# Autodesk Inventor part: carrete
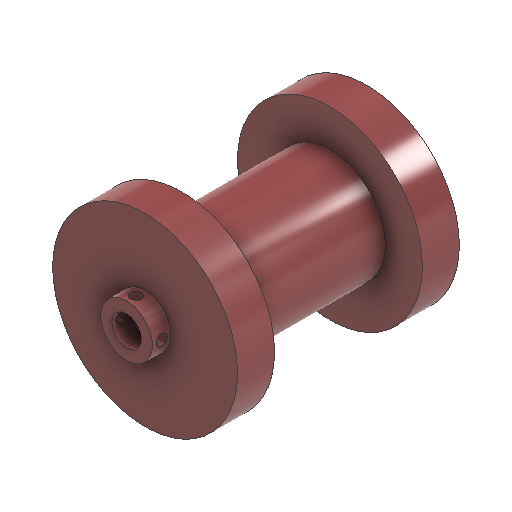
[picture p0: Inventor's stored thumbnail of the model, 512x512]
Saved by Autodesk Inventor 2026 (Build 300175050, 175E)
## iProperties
Created: 2025-06
Part Number: carrete
Material: Genérico
Document SubType Name: Modeling
Designer: piero
Density: 1 g/cm^3
Appearance: Valor por defecto
Author: piero
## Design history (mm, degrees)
sketch "Boceto1"
  geometry: C1 r 25 at (0, 0); C2 r 4 at (0, 0); C3 r 11 at (0, 0); 1 further point
  constraints: 3 centre point, 3 coincident
  dimensions: "d0" = 50 diameter of C1; "d3" = 8 diameter of C2; "d34" = 22 diameter of C3
extrude "Extrusión1" new body sketch "Boceto1" distance "d1" = 10; taper "d2" = 0 deg
sketch "Boceto5"
  geometry: C1 r 5 at (0, 0); C2 r 15 at (0, 0); 1 further point
  constraints: 2 centre point, 2 coincident
  dimensions: "d15" = 10 diameter of C1; "d16" = 30 diameter of C2
extrude "Extrusión5" join sketch "Boceto5" distance "d17" = 40; taper "d18" = 0 deg
sketch "Boceto6"
  geometry: C1 r 4 at (0, 0) reference; C2 r 25 at (0, 0); C3 r 4 at (0, 0); C4 r 5 at (0, 0) reference; C5 r 11 at (0, 0); 1 further point
  constraints: 3 centre point, 2 coincident
  dimensions: "d22" = 50 diameter of C2; "d30" = 8 diameter of C3; "d31" = 22 diameter of C5
extrude "Extrusión6" join sketch "Boceto6" distance "d23" = 10; taper "d24" = 0 deg
sketch "Boceto10"
  geometry: C1 r 7 at (0, 0); C2 r 4 at (0, 0); 1 further point
  constraints: 2 centre point, 2 coincident
  dimensions: "d41" = 14 diameter of C1; "d42" = 8 diameter of C2
extrude "Extrusión11" join sketch "Boceto10" distance "d43" = 5; taper "d44" = 0 deg
sketch "Boceto11"
  geometry: C1 r 4 at (0, 0); C2 r 7 at (0, 0); 1 further point
  constraints: 2 centre point, 2 coincident
  dimensions: "d45" = 8 diameter of C1; "d46" = 14 diameter of C2
extrude "Extrusión12" join sketch "Boceto11" distance "d47" = 5; taper "d48" = 0 deg
sketch "Boceto12"
  geometry: C1 r 1.5 at (0, 62.5); C2 r 1.5 at (0, -2.506); 1 further point
  constraints: 2 centre point
  dimensions: "d49" = 3 diameter of C1; "d50" = 3 diameter of C2
hole "Agujero1" sketch "Boceto12" at (0, 62.5) diameter "d51" = 3; stored, may be unused: countersink angle "d55" = 90 deg, drill point angle "d57" = 118 deg; dims "d52" = 6, "d53" = 4, "d54" = 2, "d56" = 8
sketch "Boceto13"
  geometry: C1 r 1.5 at (0, 62.453); C2 r 1.5 at (0, -2.49); 1 further point
  constraints: 2 centre point
  dimensions: "d58" = 3 diameter of C1; "d59" = 3 diameter of C2
hole "Agujero2" sketch "Boceto13" at (0, -2.49) diameter "d60" = 3; stored, may be unused: countersink angle "d64" = 90 deg, drill point angle "d66" = 118 deg; dims "d61" = 6, "d62" = 4, "d63" = 2, "d65" = 8
sketch "Boceto14"
  geometry: C1 r 1.5 at (0, 62.513); C2 r 1.5 at (0, -2.378); 1 further point
  constraints: 2 centre point
  dimensions: "d67" = 3 diameter of C1; "d68" = 3 diameter of C2
hole "Agujero3" sketch "Boceto14" diameter "d69" = 3; stored, may be unused: countersink angle "d73" = 90 deg, drill point angle "d75" = 118 deg; dims "d70" = 6, "d71" = 4, "d72" = 2, "d74" = 8
hole "Agujero4" sketch "Boceto14" diameter "d76" = 3; stored, may be unused: countersink angle "d80" = 90 deg, drill point angle "d82" = 118 deg; dims "d77" = 6, "d78" = 4, "d79" = 2, "d81" = 8
sketch "Boceto15"
  geometry: C1 r 1.5 at (0, -2.322); 1 further point
  constraints: 1 centre point
  dimensions: "d83" = 3 diameter of C1
hole "Agujero5" sketch "Boceto15" at (0, -2.322) diameter "d84" = 3; stored, may be unused: countersink angle "d88" = 90 deg, drill point angle "d90" = 118 deg; dims "d85" = 6, "d86" = 4, "d87" = 2, "d89" = 8
sketch "Boceto16"
  geometry: C1 r 1.5 at (0, 62.512); 1 further point
  constraints: 1 centre point
  dimensions: "d91" = 3 diameter of C1
hole "Agujero6" sketch "Boceto16" at (0, 62.512) diameter "d92" = 3; stored, may be unused: countersink angle "d96" = 90 deg, drill point angle "d98" = 118 deg; dims "d93" = 6, "d94" = 4, "d95" = 2, "d97" = 8
node "Sólido1"
